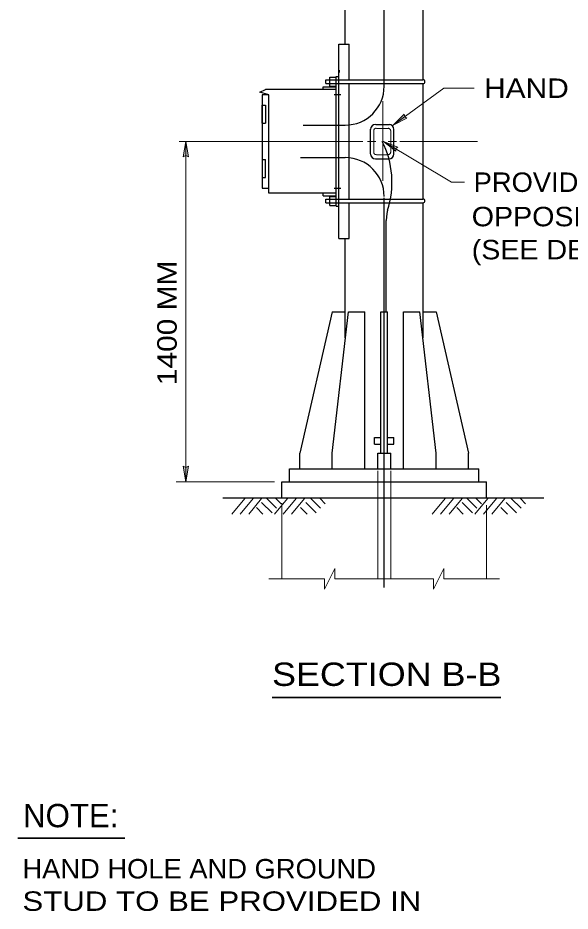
# Model space of a CAD drawing. Extents: x 312601.858 to 312602.699, y 144420.109 to 144420.704.
# Drawn here: x 312602.0705 to 312602.1557, y 144420.2331 to 144420.3709 of the extents above; entities that cross this region are included whole.
import ezdxf
from ezdxf.enums import TextEntityAlignment as Align

# ---------------------------------------------------------------- set-up
doc = ezdxf.new("R2010")
doc.units = 0
doc.header["$LTSCALE"] = 0.0012
for name, pattern in [('DOT_DASHED', [7.7, 5, -1.2, 0.3, -1.2]), ('DOTTED', [1.5, 0.3, -1.2]), ('LONG_DASH_SHORT_DASH', [9.9, 6, -1.2, 1.5, -1.2]), ('LONG_DASHED', [7.5, 6, -1.5])]:
    doc.linetypes.add(name, pattern=pattern)
for name, color, linetype, lineweight in [('1', 7, 'Continuous', 25), ('2', 7, 'Continuous', 25), ('39', 7, 'Continuous', 13)]:
    doc.layers.add(name, color=color, linetype=linetype, lineweight=lineweight)

msp = doc.modelspace()

# ---------------------------------------------------------------- hatches: boundary and pattern name
at = {"layer": '39'}
for points in [[(312602.1302, 144420.3556), (312602.1305, 144420.3554), (312602.1284, 144420.3543), (312602.1301, 144420.356)], [(312602.1302, 144420.3556), (312602.1305, 144420.3554), (312602.1284, 144420.3543), (312602.1301, 144420.356)], [(312602.0964, 144420.3496), (312602.096, 144420.3494), (312602.0964, 144420.3518), (312602.0968, 144420.3494)], [(312602.0964, 144420.3496), (312602.096, 144420.3494), (312602.0964, 144420.3518), (312602.0968, 144420.3494)], [(312602.1288, 144420.3507), (312602.1288, 144420.3503), (312602.1269, 144420.3518), (312602.1291, 144420.3509)], [(312602.0964, 144420.3015), (312602.0968, 144420.3017), (312602.0964, 144420.2993), (312602.096, 144420.3017)]]:
    msp.add_hatch(color=256, dxfattribs=at).paths.add_polyline_path(points)

# ---------------------------------------------------------------- linework, layer by layer
at = {"layer": '1', "linetype": 'LONG_DASHED'}
for p, q in [((312602.127, 144420.3603), (312602.127, 144420.3876)), ((312602.1145, 144420.3543), (312602.121, 144420.3543)), ((312602.1141, 144420.3493), (312602.121, 144420.3493)), ((312602.127, 144420.283), (312602.127, 144420.3431)), ((312602.1273, 144420.3255), (312602.1273, 144420.3396)), ((312602.1265, 144420.3255), (312602.1275, 144420.3255))]:
    msp.add_line(p, q, dxfattribs=at)
at = {"layer": '1'}
for p, q in [((312602.121, 144420.3668), (312602.121, 144420.3848)), ((312602.133, 144420.3613), (312602.133, 144420.3848)), ((312602.12, 144420.3668), (312602.1216, 144420.3668)), ((312602.12, 144420.3368), (312602.12, 144420.3668)), ((312602.1216, 144420.3613), (312602.1216, 144420.3668)), ((312602.1201, 144420.3624), (312602.1201, 144420.3628)), ((312602.118, 144420.3607), (312602.118, 144420.3613)), ((312602.1186, 144420.3603), (312602.1186, 144420.3617)), ((312602.1186, 144420.3617), (312602.1196, 144420.3617)), ((312602.1196, 144420.3618), (312602.12, 144420.3618)), ((312602.1176, 144420.3602), (312602.1196, 144420.3602)), ((312602.1176, 144420.3598), (312602.1176, 144420.3602)), ((312602.1186, 144420.3603), (312602.1196, 144420.3603)), ((312602.1216, 144420.3429), (312602.1216, 144420.3607)), ((312602.133, 144420.3429), (312602.133, 144420.3607)), ((312602.1092, 144420.359), (312602.1082, 144420.359)), ((312602.1082, 144420.359), (312602.1082, 144420.349)), ((312602.1203, 144420.359), (312602.1193, 144420.359)), ((312602.1087, 144420.3574), (312602.1087, 144420.3546)), ((312602.1082, 144420.3546), (312602.1087, 144420.3546)), ((312602.1257, 144420.3544), (312602.1278, 144420.3544)), ((312602.1249, 144420.3499), (312602.1249, 144420.3537)), ((312602.1285, 144420.3499), (312602.1285, 144420.3537)), ((312602.1082, 144420.349), (312602.1087, 144420.349)), ((312602.1087, 144420.3462), (312602.1087, 144420.349)), ((312602.1257, 144420.3491), (312602.1278, 144420.3491)), ((312602.1082, 144420.3462), (312602.1082, 144420.3446)), ((312602.1082, 144420.3446), (312602.1092, 144420.3446)), ((312602.1176, 144420.3434), (312602.1176, 144420.3438)), ((312602.1176, 144420.3434), (312602.1196, 144420.3434)), ((312602.1186, 144420.3419), (312602.1186, 144420.3433)), ((312602.1186, 144420.3433), (312602.1196, 144420.3433)), ((312602.1193, 144420.3446), (312602.1203, 144420.3446)), ((312602.118, 144420.3423), (312602.118, 144420.3429)), ((312602.1186, 144420.3419), (312602.1196, 144420.3419)), ((312602.1216, 144420.3368), (312602.1216, 144420.3423)), ((312602.133, 144420.3215), (312602.133, 144420.3423)), ((312602.1196, 144420.3418), (312602.12, 144420.3418)), ((312602.12, 144420.3368), (312602.1216, 144420.3368)), ((312602.121, 144420.3215), (312602.121, 144420.3368)), ((312602.119, 144420.3255), (312602.114, 144420.3037)), ((312602.119, 144420.3255), (312602.121, 144420.3255)), ((312602.1215, 144420.3255), (312602.124, 144420.3255)), ((312602.124, 144420.3013), (312602.124, 144420.3255)), ((312602.1265, 144420.3037), (312602.1265, 144420.3255)), ((312602.1275, 144420.3037), (312602.1275, 144420.3255)), ((312602.13, 144420.3255), (312602.1325, 144420.3255)), ((312602.13, 144420.3013), (312602.13, 144420.3255)), ((312602.133, 144420.3255), (312602.135, 144420.3255)), ((312602.135, 144420.3255), (312602.14, 144420.3037)), ((312602.1255, 144420.3051), (312602.1255, 144420.3061)), ((312602.1255, 144420.3061), (312602.1265, 144420.3061)), ((312602.1275, 144420.3061), (312602.1285, 144420.3061)), ((312602.1285, 144420.3051), (312602.1285, 144420.3061)), ((312602.1255, 144420.3051), (312602.1265, 144420.3051)), ((312602.1275, 144420.3051), (312602.1285, 144420.3051)), ((312602.114, 144420.3013), (312602.114, 144420.3037)), ((312602.119, 144420.3013), (312602.119, 144420.3037)), ((312602.126, 144420.3037), (312602.128, 144420.3037)), ((312602.126, 144420.3013), (312602.126, 144420.3037)), ((312602.128, 144420.3013), (312602.128, 144420.3037)), ((312602.135, 144420.3013), (312602.135, 144420.3037)), ((312602.14, 144420.3013), (312602.14, 144420.3037)), ((312602.1124, 144420.3013), (312602.1416, 144420.3013)), ((312602.1124, 144420.2993), (312602.1124, 144420.3013)), ((312602.1416, 144420.2993), (312602.1416, 144420.3013)), ((312602.1112, 144420.2993), (312602.1428, 144420.2993)), ((312602.1112, 144420.2968), (312602.1112, 144420.2993)), ((312602.1428, 144420.2968), (312602.1428, 144420.2993)), ((312602.1021, 144420.2968), (312602.1516, 144420.2968))]:
    msp.add_line(p, q, dxfattribs=at)
at = {"layer": '1', "linetype": 'DOT_DASHED', "lineweight": 13}
msp.add_line((312602.1268, 144420.358), (312602.1268, 144420.3457), dxfattribs=at)
at = {"layer": '1', "linetype": 'LONG_DASHED', "lineweight": 13}
for p, q in [((312602.1254, 144420.3501), (312602.1254, 144420.3535)), ((312602.1258, 144420.3538), (312602.1276, 144420.3538)), ((312602.128, 144420.3501), (312602.128, 144420.3535)), ((312602.1258, 144420.3497), (312602.1276, 144420.3497)), ((312602.126, 144420.2843), (312602.126, 144420.301)), ((312602.128, 144420.2843), (312602.128, 144420.301)), ((312602.1112, 144420.2843), (312602.1112, 144420.296)), ((312602.1428, 144420.2843), (312602.1428, 144420.2957))]:
    msp.add_line(p, q, dxfattribs=at)
at = {"layer": '1', "lineweight": 13}
for p, q in [((312602.0964, 144420.2993), (312602.0964, 144420.3518)), ((312602.1244, 144420.3518), (312602.1257, 144420.3518)), ((312602.1276, 144420.3518), (312602.1289, 144420.3518)), ((312602.0949, 144420.2993), (312602.1101, 144420.2993)), ((312602.1035, 144420.2943), (312602.1055, 144420.2967)), ((312602.1048, 144420.2943), (312602.1068, 144420.2967)), ((312602.1061, 144420.2943), (312602.1081, 144420.2967)), ((312602.1089, 144420.2967), (312602.1104, 144420.2952)), ((312602.1101, 144420.2943), (312602.1121, 144420.2967)), ((312602.1103, 144420.2967), (312602.1111, 144420.2959)), ((312602.1114, 144420.2943), (312602.1134, 144420.2967)), ((312602.1127, 144420.2943), (312602.1147, 144420.2967)), ((312602.1157, 144420.2967), (312602.1172, 144420.2952)), ((312602.1171, 144420.2967), (312602.1179, 144420.2959)), ((312602.1344, 144420.2943), (312602.1364, 144420.2967)), ((312602.1357, 144420.2943), (312602.1377, 144420.2967)), ((312602.137, 144420.2943), (312602.139, 144420.2967)), ((312602.1398, 144420.2967), (312602.1413, 144420.2952)), ((312602.141, 144420.2943), (312602.143, 144420.2967)), ((312602.1412, 144420.2967), (312602.142, 144420.2959)), ((312602.1423, 144420.2943), (312602.1443, 144420.2967)), ((312602.1436, 144420.2943), (312602.1456, 144420.2967)), ((312602.1466, 144420.2967), (312602.1481, 144420.2952)), ((312602.148, 144420.2967), (312602.1488, 144420.2959)), ((312602.1073, 144420.2953), (312602.1083, 144420.2943)), ((312602.1081, 144420.2961), (312602.1097, 144420.2945)), ((312602.1141, 144420.2953), (312602.1151, 144420.2943)), ((312602.1149, 144420.2961), (312602.1165, 144420.2945)), ((312602.1382, 144420.2953), (312602.1392, 144420.2943)), ((312602.139, 144420.2961), (312602.1406, 144420.2945)), ((312602.145, 144420.2953), (312602.146, 144420.2943)), ((312602.1458, 144420.2961), (312602.1474, 144420.2945)), ((312602.1178, 144420.2827), (312602.1194, 144420.2859)), ((312602.1194, 144420.2843), (312602.1194, 144420.2859)), ((312602.1346, 144420.2827), (312602.1362, 144420.2859)), ((312602.1362, 144420.2843), (312602.1362, 144420.2859)), ((312602.1092, 144420.2843), (312602.1178, 144420.2843)), ((312602.1178, 144420.2827), (312602.1178, 144420.2843)), ((312602.1194, 144420.2843), (312602.1346, 144420.2843)), ((312602.1346, 144420.2827), (312602.1346, 144420.2843)), ((312602.1362, 144420.2843), (312602.1448, 144420.2843))]:
    msp.add_line(p, q, dxfattribs=at)
at = {"layer": '1', "linetype": 'LONG_DASH_SHORT_DASH', "lineweight": 13}
for p, q in [((312602.1032, 144420.3518), (312602.1237, 144420.3518)), ((312602.1294, 144420.3518), (312602.1414, 144420.3518))]:
    msp.add_line(p, q, dxfattribs=at)
at = {"layer": '1', "lineweight": 35}
for p, q in [((312602.1097, 144420.266), (312602.145, 144420.266)), ((312602.0705, 144420.2443), (312602.087, 144420.2443))]:
    msp.add_line(p, q, dxfattribs=at)
at = {"layer": '1'}
for points in [[(312602.118, 144420.3613), (312602.1196, 144420.3613), (312602.133, 144420.3613)], [(312602.1196, 144420.3418), (312602.1196, 144420.3434), (312602.1196, 144420.3602), (312602.1196, 144420.3618)], [(312602.1092, 144420.3438), (312602.1092, 144420.359), (312602.1078, 144420.3594), (312602.1087, 144420.3598)], [(312602.1196, 144420.3598), (312602.1105, 144420.3598), (312602.1087, 144420.3598)], [(312602.118, 144420.3607), (312602.1196, 144420.3607), (312602.133, 144420.3607)], [(312602.1082, 144420.3546), (312602.1082, 144420.3574), (312602.1087, 144420.3574)], [(312602.1082, 144420.349), (312602.1082, 144420.3462), (312602.1087, 144420.3462)], [(312602.1196, 144420.3438), (312602.1105, 144420.3438), (312602.1092, 144420.3438)], [(312602.118, 144420.3429), (312602.1196, 144420.3429), (312602.133, 144420.3429)], [(312602.118, 144420.3423), (312602.1196, 144420.3423), (312602.133, 144420.3423)]]:
    msp.add_lwpolyline(points, dxfattribs=at)
at = {"layer": '1', "lineweight": 13}
for points in [[(312602.1409, 144420.36), (312602.1362, 144420.36), (312602.1284, 144420.3543)], [(312602.0954, 144420.3518), (312602.0991, 144420.3518), (312602.1032, 144420.3518)], [(312602.1394, 144420.3455), (312602.1374, 144420.3455), (312602.1269, 144420.3518)]]:
    msp.add_lwpolyline(points, dxfattribs=at)
at = {"layer": '1'}
for centre in [(312602.132987, 144420.361004), (312602.132987, 144420.342621)]:
    msp.add_arc(centre, 0.0003, 270, 90, dxfattribs=at)
at = {"layer": '1', "linetype": 'LONG_DASHED'}
for centre, radius, start, end in [((312602.120998, 144420.360304), 0.005994, 270, 0), ((312602.11433, 144420.345522), 0.013872, 341.70154, 26.90711), ((312602.120998, 144420.343296), 0.005994, 0, 90), ((312602.153, 144420.3372), 0.025812, 171.08507, 174.66489)]:
    msp.add_arc(centre, radius, start, end, dxfattribs=at)
at = {"layer": '1', "linetype": 'DOTTED', "lineweight": 13}
for centre, start, end in [((312602.125756, 144420.35345), 90, 180), ((312602.127606, 144420.35345), 0, 90), ((312602.125756, 144420.35012), 180, 270), ((312602.127606, 144420.35012), 270, 0)]:
    msp.add_arc(centre, 0.00037, start, end, dxfattribs=at)
at = {"layer": '1'}
for points in [[(312602.1083, 144420.3546), (312602.1082, 144420.3546)], [(312602.1083, 144420.349), (312602.1082, 144420.349)]]:
    msp.add_open_spline(points, degree=1, dxfattribs=at)
at = {"layer": '2'}
for p, q in [((312602.119, 144420.3037), (312602.1215, 144420.3255)), ((312602.135, 144420.3037), (312602.1325, 144420.3255))]:
    msp.add_line(p, q, dxfattribs=at)
for centre, start, end in [((312602.12565, 144420.35365), 90, 180), ((312602.12775, 144420.35365), 0, 90), ((312602.12565, 144420.34985), 180, 270), ((312602.12775, 144420.34985), 270, 0)]:
    msp.add_arc(centre, 0.00075, start, end, dxfattribs=at)
at = {"layer": '39'}
for points in [[(312602.1302, 144420.3556), (312602.1305, 144420.3554), (312602.1284, 144420.3543), (312602.1301, 144420.356)], [(312602.1302, 144420.3556), (312602.1305, 144420.3554), (312602.1284, 144420.3543), (312602.1301, 144420.356)], [(312602.0964, 144420.3496), (312602.096, 144420.3494), (312602.0964, 144420.3518), (312602.0968, 144420.3494)], [(312602.0964, 144420.3496), (312602.096, 144420.3494), (312602.0964, 144420.3518), (312602.0968, 144420.3494)], [(312602.1288, 144420.3507), (312602.1288, 144420.3503), (312602.1269, 144420.3518), (312602.1291, 144420.3509)], [(312602.0964, 144420.3015), (312602.0968, 144420.3017), (312602.0964, 144420.2993), (312602.096, 144420.3017)]]:
    msp.add_lwpolyline(points, close=True, dxfattribs=at)

# ---------------------------------------------------------------- texts
at = {"layer": '1'}
for s, height, width, p in [('SECTION B-B', 0.0036, 1.15, (312602.1097, 144420.2678)), ('HAND HOLE AND GROUND', 0.003, 1.05, (312602.0712, 144420.2381)), ('STUD TO BE PROVIDED IN ', 0.003, 1.2, (312602.0712, 144420.2331))]:
    msp.add_text(s, height=height, dxfattribs=dict(at, width=width)).set_placement(p)
msp.add_text('NOTE:', height=0.0036, dxfattribs=at).set_placement((312602.0713, 144420.246))
at = {"layer": '2'}
for s, width, p in [('HAND HOLE (SEE DETAIL)', 1.15, (312602.1424, 144420.3585)), ('PROVIDE GROUND STUD', 1.05, (312602.1408, 144420.344)), ('OPPOSITE HAND HOLE', 1.1, (312602.1405, 144420.3387)), ('(SEE DETAIL)', 1.1, (312602.1405, 144420.3336))]:
    msp.add_text(s, height=0.003, dxfattribs=dict(at, width=width)).set_placement(p)
at = {"layer": '2', "width": 1.15}
msp.add_text('1400 MM', height=0.003, rotation=90, dxfattribs=at).set_placement((312602.095, 144420.3238), align=Align.CENTER)

doc.saveas('drawing.dxf')
